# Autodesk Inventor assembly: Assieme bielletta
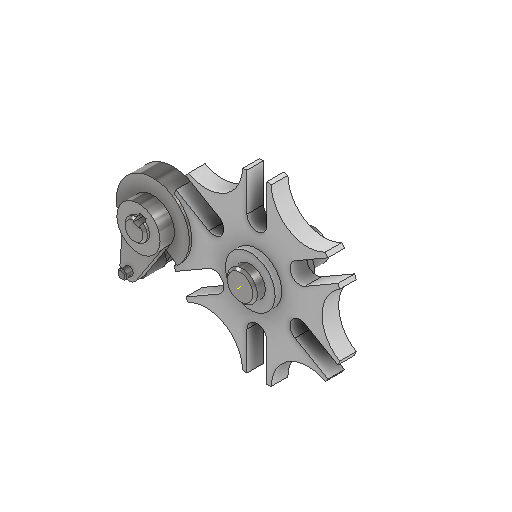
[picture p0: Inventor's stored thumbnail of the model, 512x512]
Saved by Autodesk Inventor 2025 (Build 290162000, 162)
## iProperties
Created: 2025-10
Part Number: Assieme bielletta
Document SubType Name: Assembly
Designer: 18619647
Author: 18619647
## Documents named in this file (9)
- C:\Users\Ryzen5700u\Desktop\trasm. croce di malta\Assieme croce malta.iam
- C:\Users\Ryzen5700u\Desktop\trasm. croce di malta\bielletta.ipt
- C:\Users\Ryzen5700u\Desktop\trasm. croce di malta\perno.ipt
- C:\Users\Ryzen5700u\Desktop\trasm. croce di malta\nottolino.ipt
- C:\Users\Ryzen5700u\Desktop\trasm. croce di malta\bronzina.ipt
- C:\Users\Ryzen5700u\Desktop\trasm. croce di malta\anello.ipt
- C:\Users\Ryzen5700u\Desktop\trasm. croce di malta\perno2.ipt
- C:\Users\Ryzen5700u\Desktop\trasm. croce di malta\croce di malta.ipt
- C:\Users\Ryzen5700u\Desktop\trasm. croce di malta\perno3.ipt
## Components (8 placed, 8 different names)
1. bielletta:1 — Coincidente:3, Coincidente:4, Coincidente:7, Coincidente:8, Coincidente:9, Coincidente:10, Allineato:1, Allineato:3, Rigido:2
2. perno:1 — Coincidente:1, Angolo:1, Coincidente:2, Coincidente:3, Coincidente:9
3. nottolino:1 — Coincidente:1, Angolo:1, Coincidente:2, Coincidente:4
4. bronzina:1 — Coincidente:5, Coincidente:6
5. anello:1 — Coincidente:5, Coincidente:6, Coincidente:7, Coincidente:8
6. perno2:1 — Coincidente:13, Allineato:3, Allineato:4
7. croce di malta:1 — Coincidente:14, Allineato:4
8. perno3:1 — Rigido:2
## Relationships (17: Mate 12, Flush 3, Angle 1, WeldJoint 1)
- Coincidente:1 [Mate]: perno:1 ↔ nottolino:1
- Angolo:1 [Angle]: perno:1 ↔ nottolino:1
- Coincidente:2 [Mate]: perno:1 ↔ nottolino:1
- Coincidente:3 [Mate]: bielletta:1 ↔ perno:1
- Coincidente:4 [Mate]: bielletta:1 ↔ nottolino:1
- Coincidente:5 [Mate]: bronzina:1 ↔ anello:1
- Coincidente:6 [Mate]: bronzina:1 ↔ anello:1
- Coincidente:7 [Mate]: bielletta:1 ↔ anello:1
- Coincidente:8 [Mate]: bielletta:1 ↔ anello:1
- Coincidente:9 [Mate]: bielletta:1 ↔ perno:1
- Coincidente:10 [Mate]: bielletta:1
- Allineato:1 [Flush]: bielletta:1
- Coincidente:13 [Mate]: perno2:1
- Allineato:3 [Flush]: bielletta:1 ↔ perno2:1
- Coincidente:14 [Mate]: croce di malta:1
- Allineato:4 [Flush]: perno2:1 ↔ croce di malta:1
- Rigido:2 [WeldJoint]: bielletta:1 ↔ perno3:1
